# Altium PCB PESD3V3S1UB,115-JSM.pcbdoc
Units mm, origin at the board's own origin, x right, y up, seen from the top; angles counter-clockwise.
Board outline 14.6 x 13.8 mm, 2 copper layers (Top Layer, Bottom Layer), stack 0 mm thick; 1 components, 0 nets, 2 pads, 0 vias.
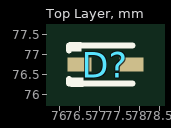
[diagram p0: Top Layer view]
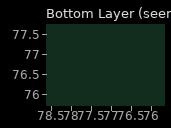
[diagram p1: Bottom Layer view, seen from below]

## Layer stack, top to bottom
Top Layer: signal copper (thickness not stored)
Bottom Layer: signal copper (thickness not stored)

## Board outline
84.45,69.85 69.85,69.85 69.85,83.654 84.45,83.654

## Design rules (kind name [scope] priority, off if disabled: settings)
PasteMaskExpansion "Paste Mask Expansion" [All] p1: expansion=0
SolderMaskExpansion "Solder Mask Expansion" [IsVia] p1: expansion=-25.4 istentingtop=TRUE
SolderMaskExpansion "Solder Mask Expansion" [All] p2: expansion=0.051 istentingtop=FALSE

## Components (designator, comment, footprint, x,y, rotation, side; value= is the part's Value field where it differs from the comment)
D? "PESD3V3S1UB,115-JSM" SOD-523_L1.2-W0.8-LS1.6-RD 77.15,76.752 r0 top

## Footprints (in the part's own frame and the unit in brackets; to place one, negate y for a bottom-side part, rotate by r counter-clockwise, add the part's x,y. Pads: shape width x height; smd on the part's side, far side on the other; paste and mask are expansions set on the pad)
SOD-523_L1.2-W0.8-LS1.6-RD [mm]
  rect 0.6x0.36 smd: 1(-0.65,0) 2(0.65,0)
  silkscreen extent -0.91,-0.55 0.68,0.55

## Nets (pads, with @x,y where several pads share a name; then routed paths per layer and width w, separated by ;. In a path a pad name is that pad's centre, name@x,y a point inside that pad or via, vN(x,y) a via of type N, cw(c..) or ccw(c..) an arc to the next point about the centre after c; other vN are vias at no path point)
pads on no net: D?.1 D?.2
